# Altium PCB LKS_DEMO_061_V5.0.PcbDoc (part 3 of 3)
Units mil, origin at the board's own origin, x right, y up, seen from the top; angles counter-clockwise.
Board outline 4534.65 x 3225.59 mil, 2 copper layers (Top Layer, Bottom Layer); 196 components, 108 nets, 502 pads, 1380 vias.
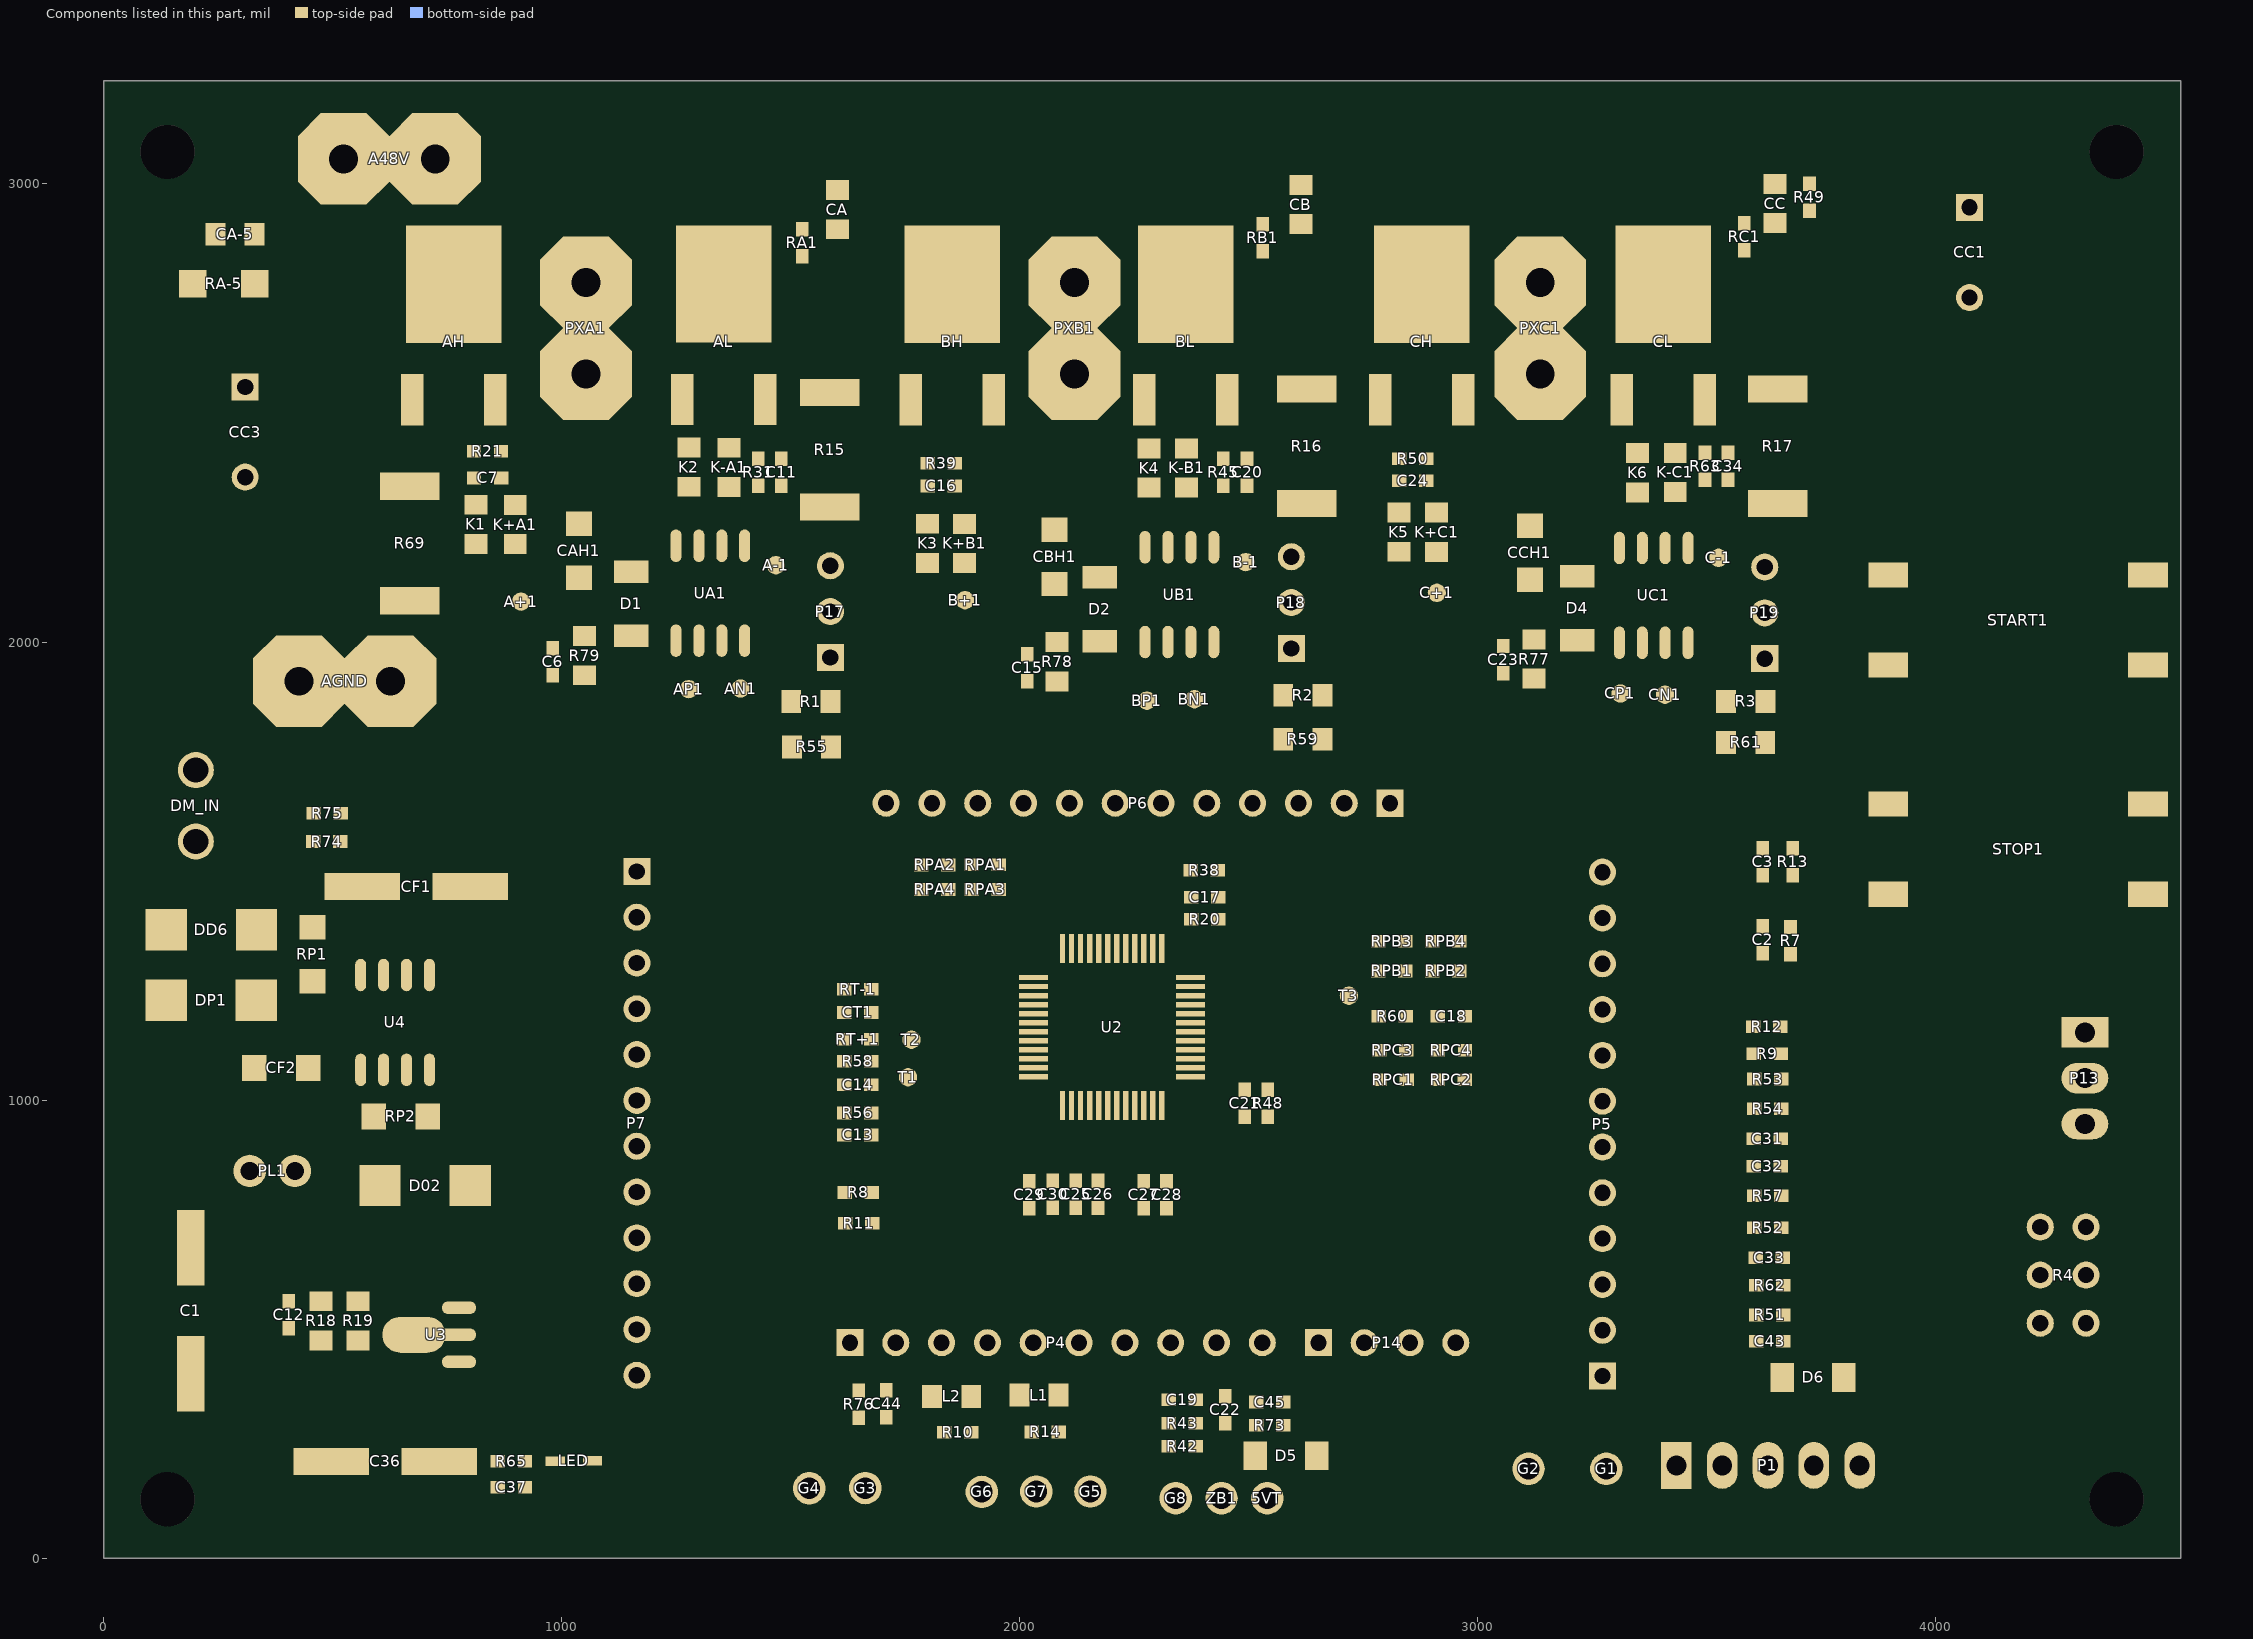
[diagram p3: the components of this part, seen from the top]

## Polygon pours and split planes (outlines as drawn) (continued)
BX on Bottom Solder "Bottom Layer-No Net" (solid): 2050,2900 2031.89,2881.89 2031.89,2856.69 2031.89,2613.39 2001.18,2582.68 1998.82,2580.32 1896.85,2580.32 1880.32,2580.32 1868.11,2568.11 1865.35,2565.35 1865.35,2471.26 1865.35,2468.9 1873.62,2460.63 1874.02,2460.24 2195.67,2460.24 2206.69,2460.24 2215.35,2468.9 2218.9,2472.44 2218.9,2599.21 2218.9,2618.5 2242.52,2642.13 2243.7,2643.31 2448.82,2643.31 2467.32,2643.31 2483.46,2659.45 2485.04,2661.02 2485.04,2880.32 2485.04,2889.37 2474.41,2900
AX on Bottom Solder "Bottom Layer-No Net" (solid): 1005.91,2902.76 968.5,2865.35 968.5,2840.16 968.5,2630.32 936.22,2598.03 933.46,2595.28 829.92,2595.28 829.13,2595.28 810.63,2576.77 807.87,2574.02 807.87,2493.7 807.87,2483.46 818.9,2472.44 819.68,2471.65 1139.76,2471.65 1193.7,2471.65 1205.51,2483.46 1205.91,2483.86 1205.91,2600.79 1205.91,2611.81 1225.2,2631.1 1233.86,2639.76 1397.24,2639.76 1450.39,2639.76 1463.39,2652.76 1463.39,2891.73 1463.39,2893.31 1454.33,2902.36

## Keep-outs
Keep-Out Layer:
  lines w5: 0,3138.98 cw(c86.61,3138.98) 86.61,3225.59 ; 0,3150 0,92.13 ccw(c91.73,92.13) 91.73,0.39 ; 75.59,3225.59 4042.13,3225.59 4448.03,3225.59 ; 91.73,0 3615.31,0 4448.43,0 ; 4448.03,3225.2 cw(c4448.03,3138.58) 4534.65,3138.58 ; 4448.43,0.39 ccw(c4448.43,87.01) 4535.04,87.01 ; 4534.65,87.01 4534.65,3143.7

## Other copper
Top Layer:
  pour cut-out: -36.22,2985.83 -36.22,2949.61 -26.38,2939.76 273.62,2939.76 273.62,2982.68 270.47,2985.83
  pour cut-out: 647.24,2177.56 647.24,2124.02 736.61,2124.02 738.19,2125.59 740.16,2123.62 823.85,2033.79 822.99,1961.29 823.42,1799.55 823.85,1720.62 876.77,1673.62 1163.78,1673.62 1593.31,1244.09 1593.31,1224.41 1637.01,1224.41 1639.76,1227.17 1639.76,1261.02 1620.47,1261.02 1171.65,1709.84 891.67,1709.84 857.31,1826.58 857.74,1990.46 844.01,2083.98 772.05,2155.91 750,2177.95
  pour cut-out: -26.38,318.11 305.12,318.11 360.63,262.6 360.63,-36.22 -24.8,-36.22 -26.38,-34.65
  pour cut-out: 4581.5,341.34 4579.92,342.91 4125.2,342.91 4062.6,280.31 4062.6,5.91 4551.57,5.91 4587.4,41.73
  pour cut-out: 4204.33,3253.54 4198.03,3247.24 4198.03,2855.91 4199.61,2854.33 4287.8,2854.33 4287.8,3240.94 4268.9,3259.84
Bottom Layer:
  pour cut-out: -36.22,2985.83 -36.22,2949.61 -26.38,2939.76 273.62,2939.76 273.62,2982.68 270.47,2985.83
  pour cut-out: -27.17,317.32 304.33,317.32 359.84,261.81 359.84,-37.01 -25.59,-37.01 -27.17,-35.43
  pour cut-out: 4581.69,341.93 4580.12,343.5 4125.39,343.5 4062.8,280.91 4062.8,6.5 4551.77,6.5 4587.6,42.32
  pour cut-out: 4204.33,3252.76 4198.03,3246.46 4198.03,2855.12 4199.61,2853.54 4287.8,2853.54 4287.8,3240.16 4268.9,3259.06

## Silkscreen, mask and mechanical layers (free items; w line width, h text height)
Top Overlay:
  drawing of 457 lines, arcs and shapes, not listed
  text "LKS_DEMO_061_V5.0" at 2668.11,3065.75 h80
  text "+48V" at 894.09,3043.31 h100
  text "C" at 3105.51,2942.91 h100
  text "B" at 2098.03,2935.83 h100
  text "A" at 1047.64,2930.71 h100
  text "START" at 3821.33,2317.8 h100
  text "P19" at 3750,2047.24 h100 r90
  text "P18" at 2716.54,2042.91 h100 r90
  text "PGND" at 334.65,2033.86 h100
  text "P17" at 1711.42,2013.39 h100 r90
  text "DM_IN" at 39.09,1836.63 h100
  text "STOP" at 3608.09,1632.84 h100
  text "P6" at 1548.82,1616.14 h100
  text "P7" at 1118.5,1573.62 h100
  text "P5" at 3228.35,1562.2 h100
  text "BP" at 2284.56,1551.69 h60
  text "AN" at 2180.41,1550.74 h60
  text "BN" at 2377.58,1550.85 h60
  text "AP" at 2082.43,1550.11 h60
  text "CP" at 2477.95,1550 h60
  text "CN" at 2572.05,1550 h60
  text "GND" at 4058.22,1125.89 h70
  text "TXD" at 4059.43,1029 h70
  text "RXD" at 4058.83,921.15 h70
  text "R4" at 3993.31,700 h100
  text "P4" at 1581.5,530.31 h100
  text "P14" at 3018.11,438.98 h100
  text "5V" at 2613.78,373.62 h60
  text "CLK" at 2690.94,373.23 h60
  text "DIO" at 2810.63,373.23 h60
  text "GND" at 2915.75,373.23 h60
  text "P1" at 3230.31,264.47 h100
  text "GND" at 1480.31,56.69 h60
  text "GND" at 3350.39,46.46 h70
  text "C" at 3525.59,45.67 h70
  text "B" at 3628.74,44.09 h70
  text "5VH" at 3813.39,44.09 h70
  text "A" at 3729.13,42.91 h70
  text "5V" at 2515.75,31.89 h60
  text "ZB" at 2416.54,29.92 h60
  text "GND" at 2279.02,28.61 h60
Bottom Overlay:
  drawing of 452 lines, arcs and shapes, not listed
